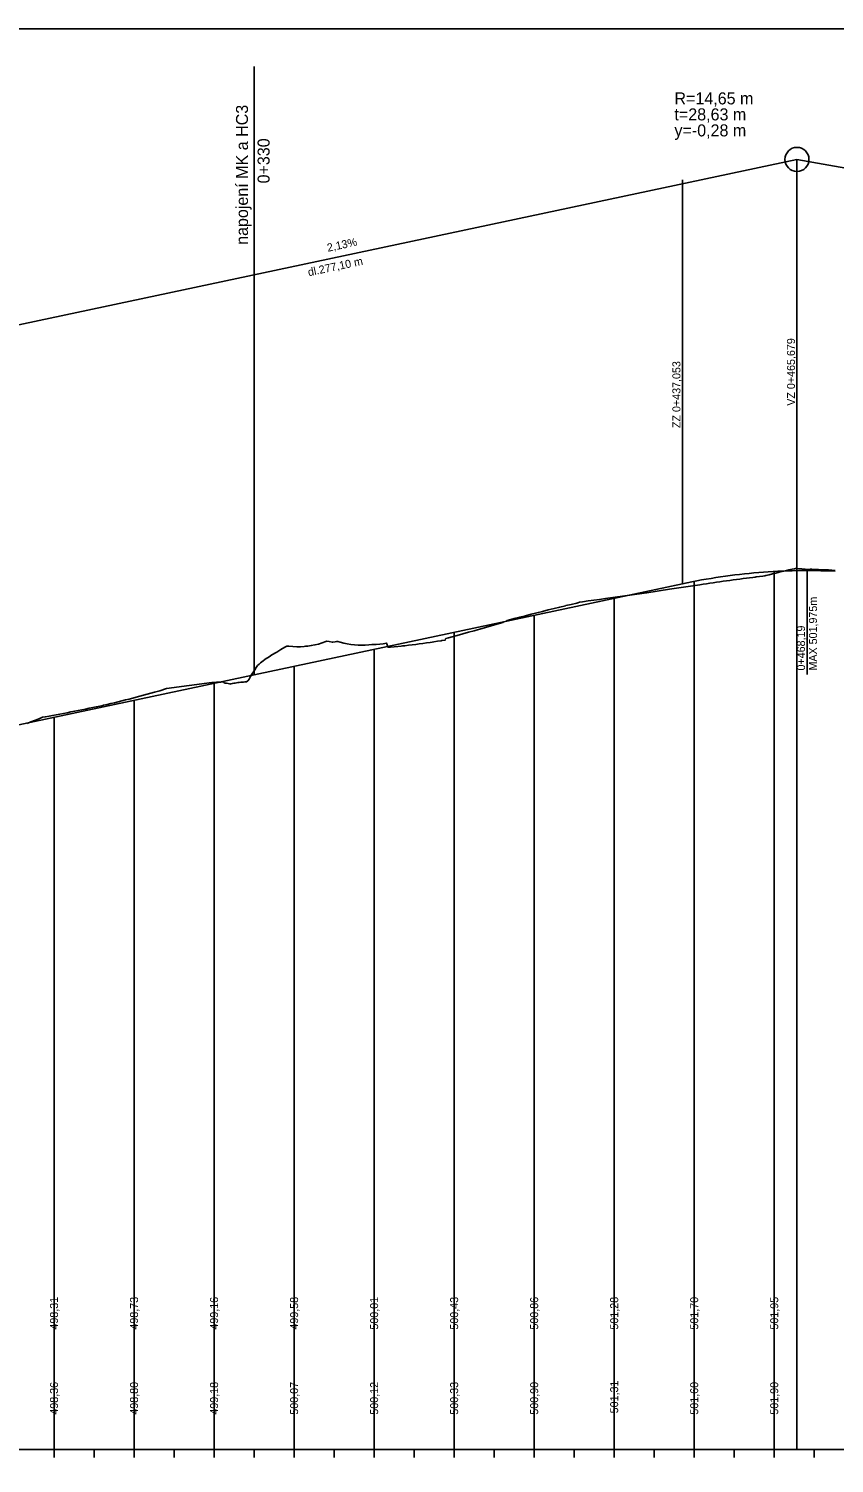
# Model space of a CAD drawing. Extents: x -632716 to -629545, y -1094726 to -1088285.
# Drawn here: x -632144.2 to -631942.9, y -1088643.3 to -1088284.6 of the extents above; entities that cross this region are included whole.
import ezdxf

# ---------------------------------------------------------------- set-up
doc = ezdxf.new("R2010")
doc.units = 0
for name, color, linetype in [('20', 7, 'Continuous'), ('Default', 7, 'Continuous'), ('formát', 7, 'Continuous'), ('NIVELETA_VYSKY', 7, 'Continuous'), ('REZ_TENKA', 7, 'Continuous'), ('REZ_TLUSTA', 7, 'Continuous'), ('SKLONY_NIVELETA', 7, 'Continuous'), ('SKLONY_POPIS', 7, 'Continuous'), ('TECNY_NIVELETA', 7, 'Continuous'), ('TEREN_VYSKY', 7, 'Continuous'), ('VOZOVKA', 7, 'Continuous')]:
    doc.layers.add(name, color=color, linetype=linetype)

msp = doc.modelspace()

# ---------------------------------------------------------------- linework, layer by layer
at = {"layer": '20'}
for points in [[(-631957.9, -1088420.31), (-631957.9, -1088589.83), (-631957.9, -1088639.83), (-631957.9, -1088579.83)], [(-631977.9, -1088422.79), (-631977.9, -1088589.83), (-631977.9, -1088639.83), (-631977.9, -1088579.83)], [(-631997.9, -1088427.01), (-631997.9, -1088589.83), (-631997.9, -1088639.83), (-631997.9, -1088579.83)], [(-632017.9, -1088431.27), (-632017.9, -1088589.83), (-632017.9, -1088639.83), (-632017.9, -1088579.83)], [(-632037.9, -1088435.52), (-632037.9, -1088589.83), (-632037.9, -1088639.83), (-632037.9, -1088579.83)], [(-632057.9, -1088439.77), (-632057.9, -1088589.83), (-632057.9, -1088639.83), (-632057.9, -1088579.83)], [(-632077.9, -1088444.02), (-632077.9, -1088589.83), (-632077.9, -1088639.83), (-632077.9, -1088579.83)], [(-632097.9, -1088448.27), (-632097.9, -1088589.83), (-632097.9, -1088639.83), (-632097.9, -1088579.83)], [(-632117.9, -1088452.52), (-632117.9, -1088589.83), (-632117.9, -1088639.83), (-632117.9, -1088579.83)], [(-632137.9, -1088456.77), (-632137.9, -1088589.83), (-632137.9, -1088639.83), (-632137.9, -1088579.83)]]:
    msp.add_lwpolyline(points, dxfattribs=at)
at = {"layer": 'Default'}
msp.add_line((-632184.04, -1088466.57), (-631980.85, -1088423.39), dxfattribs=at)
msp.add_line((-632184.04, -1088466.57), (-631980.85, -1088423.39), dxfattribs=at)
msp.add_lwpolyline([(-631980.85, -1088423.39), (-631979.66, -1088423.14), (-631978.46, -1088422.9), (-631977.27, -1088422.67), (-631976.08, -1088422.45), (-631974.89, -1088422.24), (-631973.69, -1088422.04), (-631972.5, -1088421.85), (-631971.31, -1088421.67), (-631970.12, -1088421.5), (-631968.92, -1088421.34), (-631967.73, -1088421.19), (-631966.54, -1088421.05), (-631965.34, -1088420.92), (-631964.15, -1088420.79), (-631962.96, -1088420.68), (-631961.77, -1088420.58), (-631960.57, -1088420.48), (-631959.38, -1088420.4), (-631958.19, -1088420.33), (-631957, -1088420.26), (-631955.8, -1088420.21), (-631954.61, -1088420.16), (-631953.42, -1088420.13), (-631951.03, -1088420.09), (-631949.84, -1088420.08), (-631948.65, -1088420.09), (-631947.45, -1088420.1), (-631946.26, -1088420.12), (-631945.07, -1088420.16), (-631943.88, -1088420.2), (-631942.68, -1088420.25)], dxfattribs=at)
msp.add_lwpolyline([(-631980.85, -1088423.39), (-631979.66, -1088423.14), (-631978.46, -1088422.9), (-631977.27, -1088422.67), (-631976.08, -1088422.45), (-631974.89, -1088422.24), (-631973.69, -1088422.04), (-631972.5, -1088421.85), (-631971.31, -1088421.67), (-631970.12, -1088421.5), (-631968.92, -1088421.34), (-631967.73, -1088421.19), (-631966.54, -1088421.05), (-631965.34, -1088420.92), (-631964.15, -1088420.79), (-631962.96, -1088420.68), (-631961.77, -1088420.58), (-631960.57, -1088420.48), (-631959.38, -1088420.4), (-631958.19, -1088420.33), (-631957, -1088420.26), (-631955.8, -1088420.21), (-631954.61, -1088420.16), (-631953.42, -1088420.13), (-631951.03, -1088420.09), (-631949.84, -1088420.08), (-631948.65, -1088420.09), (-631947.45, -1088420.1), (-631946.26, -1088420.12), (-631945.07, -1088420.16), (-631943.88, -1088420.2), (-631942.68, -1088420.25)], dxfattribs=at)
at = {"layer": 'formát'}
msp.add_lwpolyline([(-632571.12, -1088878.64), (-631731.12, -1088878.64), (-631731.12, -1088284.64), (-632571.12, -1088284.64)], close=True, dxfattribs=at)
at = {"layer": 'REZ_TENKA'}
for p, q in [((-632137.9, -1088641.83), (-632137.9, -1088639.83)), ((-632127.9, -1088641.83), (-632127.9, -1088639.83)), ((-632107.9, -1088641.83), (-632107.9, -1088639.83)), ((-632097.9, -1088641.83), (-632097.9, -1088639.83)), ((-632087.9, -1088641.83), (-632087.9, -1088639.83)), ((-632077.9, -1088641.83), (-632077.9, -1088639.83)), ((-632067.9, -1088641.83), (-632067.9, -1088639.83)), ((-632057.9, -1088641.83), (-632057.9, -1088639.83)), ((-632047.9, -1088641.83), (-632047.9, -1088639.83)), ((-632037.9, -1088641.83), (-632037.9, -1088639.83)), ((-632027.9, -1088641.83), (-632027.9, -1088639.83)), ((-632007.9, -1088641.83), (-632007.9, -1088639.83)), ((-631997.9, -1088641.83), (-631997.9, -1088639.83)), ((-631987.9, -1088641.83), (-631987.9, -1088639.83)), ((-631977.9, -1088641.83), (-631977.9, -1088639.83)), ((-631967.9, -1088641.83), (-631967.9, -1088639.83)), ((-631957.9, -1088641.83), (-631957.9, -1088639.83)), ((-631947.9, -1088641.83), (-631947.9, -1088639.83))]:
    msp.add_line(p, q, dxfattribs=at)
at = {"layer": 'REZ_TLUSTA'}
for p, q in [((-632117.9, -1088641.83), (-632117.9, -1088637.83)), ((-632017.9, -1088641.83), (-632017.9, -1088637.83)), ((-632417.9, -1088639.83), (-631797.9, -1088639.83))]:
    msp.add_line(p, q, dxfattribs=at)
at = {"layer": 'SKLONY_NIVELETA'}
for p, q in [((-632087.9, -1088294.08), (-632087.9, -1088446.14)), ((-632229.32, -1088376.2), (-631952.22, -1088317.31)), ((-631952.22, -1088317.31), (-631952.22, -1088639.83)), ((-631952.22, -1088317.31), (-631854.75, -1088334.68)), ((-632184.04, -1088466.57), (-631980.85, -1088423.39))]:
    msp.add_line(p, q, dxfattribs=at)
msp.add_lwpolyline([(-631980.85, -1088423.39), (-631979.66, -1088423.14), (-631978.46, -1088422.9), (-631977.27, -1088422.67), (-631976.08, -1088422.45), (-631974.89, -1088422.24), (-631973.69, -1088422.04), (-631972.5, -1088421.85), (-631971.31, -1088421.67), (-631970.12, -1088421.5), (-631968.92, -1088421.34), (-631967.73, -1088421.19), (-631966.54, -1088421.05), (-631965.34, -1088420.92), (-631964.15, -1088420.79), (-631962.96, -1088420.68), (-631961.77, -1088420.58), (-631960.57, -1088420.48), (-631959.38, -1088420.4), (-631958.19, -1088420.33), (-631957, -1088420.26), (-631955.8, -1088420.21), (-631954.61, -1088420.16), (-631953.42, -1088420.13), (-631951.03, -1088420.09), (-631949.84, -1088420.08), (-631948.65, -1088420.09), (-631947.45, -1088420.1), (-631946.26, -1088420.12), (-631945.07, -1088420.16), (-631943.88, -1088420.2), (-631942.68, -1088420.25)], dxfattribs=at)
msp.add_circle((-631952.22, -1088317.31), 3, dxfattribs=at)
at = {"layer": 'TECNY_NIVELETA'}
for p, q in [((-631952.22, -1088317.31), (-631952.22, -1088317.31)), ((-631980.85, -1088423.39), (-631980.85, -1088322.39)), ((-631949.71, -1088420.08), (-631949.71, -1088446.08))]:
    msp.add_line(p, q, dxfattribs=at)
at = {"layer": 'VOZOVKA'}
msp.add_lwpolyline([(-632144.6, -1088458.3), (-632143.69, -1088457.94), (-632142.78, -1088457.57), (-632141.87, -1088457.2), (-632140.96, -1088456.82), (-632140.79, -1088456.75), (-632140.05, -1088456.62), (-632139.15, -1088456.47), (-632138.24, -1088456.3), (-632137.33, -1088456.14), (-632136.42, -1088455.97), (-632135.51, -1088455.8), (-632134.6, -1088455.62), (-632133.69, -1088455.44), (-632132.78, -1088455.26), (-632131.88, -1088455.08), (-632130.97, -1088454.89), (-632130.06, -1088454.7), (-632130.06, -1088454.7), (-632129.15, -1088454.52), (-632128.24, -1088454.34), (-632127.33, -1088454.16), (-632126.42, -1088453.97), (-632125.91, -1088453.87), (-632125.52, -1088453.78), (-632124.61, -1088453.56), (-632123.7, -1088453.35), (-632122.79, -1088453.12), (-632121.88, -1088452.9), (-632120.97, -1088452.67), (-632120.06, -1088452.43), (-632119.15, -1088452.2), (-632118.24, -1088451.96), (-632117.33, -1088451.72), (-632116.43, -1088451.47), (-632115.52, -1088451.23), (-632114.61, -1088450.98), (-632113.7, -1088450.74), (-632112.79, -1088450.49), (-632111.48, -1088450.13), (-632109.78, -1088449.58), (-632098.48, -1088448.11), (-632098.34, -1088448.1), (-632097.99, -1088448.07), (-632097.63, -1088448.05), (-632097.27, -1088448.02), (-632096.91, -1088447.99), (-632096.56, -1088447.97), (-632096.2, -1088447.95), (-632095.84, -1088447.93), (-632095.66, -1088447.92), (-632095.49, -1088448.07), (-632095.39, -1088448.16), (-632095.13, -1088448.21), (-632094.77, -1088448.28), (-632094.41, -1088448.35), (-632094.06, -1088448.43), (-632093.93, -1088448.46), (-632093.7, -1088448.4), (-632093.34, -1088448.33), (-632092.99, -1088448.26), (-632092.64, -1088448.2), (-632092.29, -1088448.14), (-632091.94, -1088448.09), (-632091.59, -1088448.05), (-632091.24, -1088448.01), (-632090.89, -1088447.98), (-632090.55, -1088447.96), (-632090.54, -1088447.96), (-632090.18, -1088447.93), (-632089.83, -1088447.91), (-632089.79, -1088447.91), (-632089.48, -1088447.69), (-632089.36, -1088447.61), (-632089.13, -1088447.2), (-632088.78, -1088446.58), (-632088.43, -1088445.99), (-632088.08, -1088445.42), (-632087.73, -1088444.87), (-632087.37, -1088444.33), (-632087.03, -1088443.85), (-632087.01, -1088443.83), (-632086.66, -1088443.5), (-632086.3, -1088443.19), (-632085.94, -1088442.9), (-632085.59, -1088442.62), (-632085.23, -1088442.36), (-632084.87, -1088442.11), (-632084.51, -1088441.87), (-632084.16, -1088441.64), (-632083.8, -1088441.41), (-632083.44, -1088441.19), (-632083.09, -1088440.98), (-632082.73, -1088440.77), (-632082.2, -1088440.45), (-632081.2, -1088439.86), (-632080.2, -1088439.26), (-632079.69, -1088438.95), (-632079.2, -1088439.01), (-632078.2, -1088439.11), (-632077.2, -1088439.15), (-632076.3, -1088439.13), (-632075.4, -1088439.05), (-632075.02, -1088439), (-632074.5, -1088438.96), (-632073.6, -1088438.84), (-632072.7, -1088438.67), (-632071.8, -1088438.45), (-632070.9, -1088438.17), (-632070, -1088437.85), (-632069.76, -1088437.75), (-632069.1, -1088437.86), (-632068.39, -1088437.98), (-632068.2, -1088437.95), (-632067.6, -1088437.87), (-632067.3, -1088437.86), (-632066.94, -1088437.84), (-632066.4, -1088437.99), (-632065.5, -1088438.21), (-632064.6, -1088438.39), (-632063.7, -1088438.54), (-632062.8, -1088438.64), (-632061.9, -1088438.7), (-632061, -1088438.73), (-632060.1, -1088438.72), (-632059.2, -1088438.66), (-632058.45, -1088438.59), (-632058.3, -1088438.59), (-632057.4, -1088438.57), (-632056.5, -1088438.5), (-632055.6, -1088438.38), (-632054.77, -1088438.23), (-632054.7, -1088438.44), (-632054.56, -1088438.88), (-632054.45, -1088439.27), (-632053.8, -1088439.22), (-632052.9, -1088439.14), (-632052, -1088439.06), (-632051.1, -1088438.97), (-632050.79, -1088438.93), (-632050.2, -1088438.87), (-632049.3, -1088438.78), (-632048.4, -1088438.67), (-632047.5, -1088438.56), (-632046.6, -1088438.44), (-632045.69, -1088438.31), (-632044.78, -1088438.18), (-632043.87, -1088438.04), (-632043.39, -1088437.97), (-632042.96, -1088437.9), (-632042.05, -1088437.76), (-632041.14, -1088437.62), (-632040.99, -1088437.59), (-632040.24, -1088437.47), (-632040.1, -1088437.45), (-632040.06, -1088437.19), (-632039.98, -1088437.11), (-632039.33, -1088436.93), (-632038.42, -1088436.68), (-632037.51, -1088436.42), (-632036.6, -1088436.16), (-632035.75, -1088435.92), (-632034.33, -1088435.52), (-632032.9, -1088435.14), (-632032.62, -1088435.07), (-632031.47, -1088434.72), (-632030.05, -1088434.29), (-632028.62, -1088433.87), (-632027.2, -1088433.45), (-632025.77, -1088433.04), (-632025.45, -1088432.95), (-632024.77, -1088432.74), (-632024.76, -1088432.73), (-632024.74, -1088432.61), (-632024.74, -1088432.59), (-632024.35, -1088432.49), (-632022.92, -1088432.11), (-632021.5, -1088431.74), (-632020.07, -1088431.37), (-632018.64, -1088431.01), (-632017.22, -1088430.65), (-632015.79, -1088430.29), (-632014.37, -1088429.93), (-632012.94, -1088429.58), (-632011.52, -1088429.23), (-632010.09, -1088428.89), (-632010, -1088428.86), (-632008.66, -1088428.55), (-632007.24, -1088428.22), (-632006.95, -1088428.15), (-632006.56, -1088428.02), (-632005.81, -1088427.91), (-632004.39, -1088427.7), (-632002.96, -1088427.49), (-632001.54, -1088427.29), (-632000.11, -1088427.08), (-631990.95, -1088425.79), (-631989.8, -1088425.62), (-631989.76, -1088425.62), (-631984.09, -1088424.77), (-631976.48, -1088423.64), (-631975.65, -1088423.52), (-631974.82, -1088423.39), (-631973.98, -1088423.27), (-631973.15, -1088423.15), (-631972.32, -1088423.02), (-631971.48, -1088422.9), (-631970.65, -1088422.78), (-631969.82, -1088422.66), (-631968.98, -1088422.55), (-631968.15, -1088422.43), (-631967.32, -1088422.32), (-631966.48, -1088422.21), (-631965.67, -1088422.1), (-631964.85, -1088422), (-631964.04, -1088421.9), (-631963.22, -1088421.8), (-631962.65, -1088421.74), (-631962.4, -1088421.7), (-631961.59, -1088421.6), (-631960.77, -1088421.49), (-631960.28, -1088421.43), (-631959.96, -1088421.34), (-631959.14, -1088421.13), (-631958.32, -1088420.93), (-631957.51, -1088420.72), (-631956.69, -1088420.52), (-631955.88, -1088420.33), (-631955.06, -1088420.14), (-631954.24, -1088419.95), (-631953.43, -1088419.77), (-631952.92, -1088419.66), (-631952.81, -1088419.63), (-631952.61, -1088419.61), (-631952.43, -1088419.59), (-631951.8, -1088419.62), (-631951.77, -1088419.62), (-631950.98, -1088419.69), (-631950.16, -1088419.77), (-631949.33, -1088419.85), (-631949.14, -1088419.87), (-631948.91, -1088419.73), (-631948.5, -1088419.75), (-631947.66, -1088419.79), (-631946.83, -1088419.82), (-631946, -1088419.87), (-631945.16, -1088419.91), (-631944.33, -1088419.95), (-631943.5, -1088420), (-631942.66, -1088420.05)], dxfattribs=at)

# ---------------------------------------------------------------- texts
at = {"layer": 'NIVELETA_VYSKY'}
for s, p in [('498,31', (-632136.9, -1088609.83)), ('498,73', (-632116.9, -1088609.83)), ('499,16', (-632096.9, -1088609.83)), ('499,58', (-632076.9, -1088609.83)), ('500,01', (-632056.9, -1088609.83)), ('500,43', (-632036.9, -1088609.83)), ('500,86', (-632016.9, -1088609.83)), ('501,28', (-631996.9, -1088609.83)), ('501,70', (-631976.9, -1088609.83)), ('501,95', (-631956.9, -1088609.83))]:
    msp.add_text(s, height=2, rotation=90, dxfattribs=at).set_placement(p)
at = {"layer": 'SKLONY_POPIS'}
for s, p in [('R=14,65 m', (-631982.84, -1088303.56)), ('t=28,63 m', (-631982.84, -1088307.56)), ('y=-0,28 m', (-631982.84, -1088311.56))]:
    msp.add_text(s, height=3, dxfattribs=at).set_placement(p)
for s, height, rotation, p in [('napojení MK a HC3', 3, 90, (-632089.42, -1088338.68)), ('0+330', 3, 90, (-632084.02, -1088323.32)), ('2,13%', 2, 11.9985, (-632069.44, -1088340.41)), ('dl.277,10 m', 2, 11.9985, (-632074.23, -1088346.53)), ('VZ 0+465,679', 2, 90, (-631952.72, -1088378.89)), ('ZZ 0+437,053', 2, 90, (-631981.35, -1088384.47)), ('MAX 501,975m', 2, 90, (-631947.21, -1088445.08)), ('0+468,19', 2, 90, (-631950.21, -1088445.08))]:
    msp.add_text(s, height=height, rotation=rotation, dxfattribs=at).set_placement(p)
at = {"layer": 'TEREN_VYSKY'}
for s, p in [('498,36', (-632136.9, -1088631.09)), ('498,80', (-632116.9, -1088631.09)), ('499,18', (-632096.9, -1088631.09)), ('500,07', (-632076.9, -1088631.09)), ('500,12', (-632056.9, -1088631.09)), ('500,33', (-632036.9, -1088631.09)), ('500,90', (-632016.9, -1088631.09)), ('501,31', (-631996.9, -1088630.76)), ('501,60', (-631976.9, -1088631.09)), ('501,90', (-631956.9, -1088631.09))]:
    msp.add_text(s, height=2, rotation=90, dxfattribs=at).set_placement(p)

doc.saveas('drawing.dxf')
